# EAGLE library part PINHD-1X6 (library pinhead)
PIN HEADER
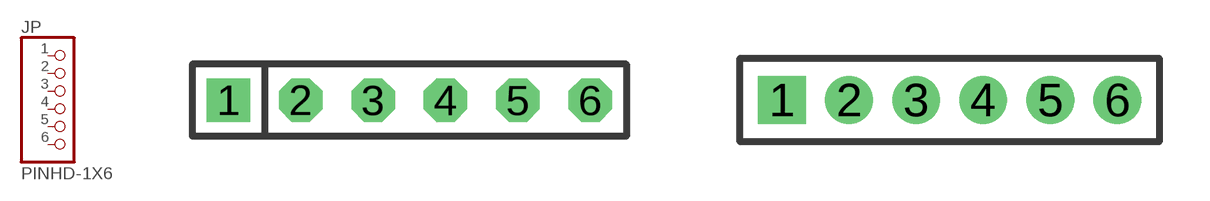
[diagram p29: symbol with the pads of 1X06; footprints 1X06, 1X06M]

Designator prefix JP

## PINHD-1X6  [1X06]
1  1  pas
2  2  pas
3  3  pas
4  4  pas
5  5  pas
6  6  pas

## PINHD-1X6M  [1X06M]
Pads as for 1X06

## Footprint 1X06 (pad centres in mm)
PIN HEADER - 0.1"
drill 1.016 square: 1 -6.35,0
drill 1.016 octagon: 2 -3.81,0; 3 -1.27,0; 4 1.27,0; 5 3.81,0; 6 6.35,0

## Footprint 1X06M (pad centres in mm)
PIN HEADER - 2MM"
drill 0.914 square: 1 -5,0
drill 0.914 round: 2 -3,0; 3 -1,0; 4 1,0; 5 3,0; 6 5,0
